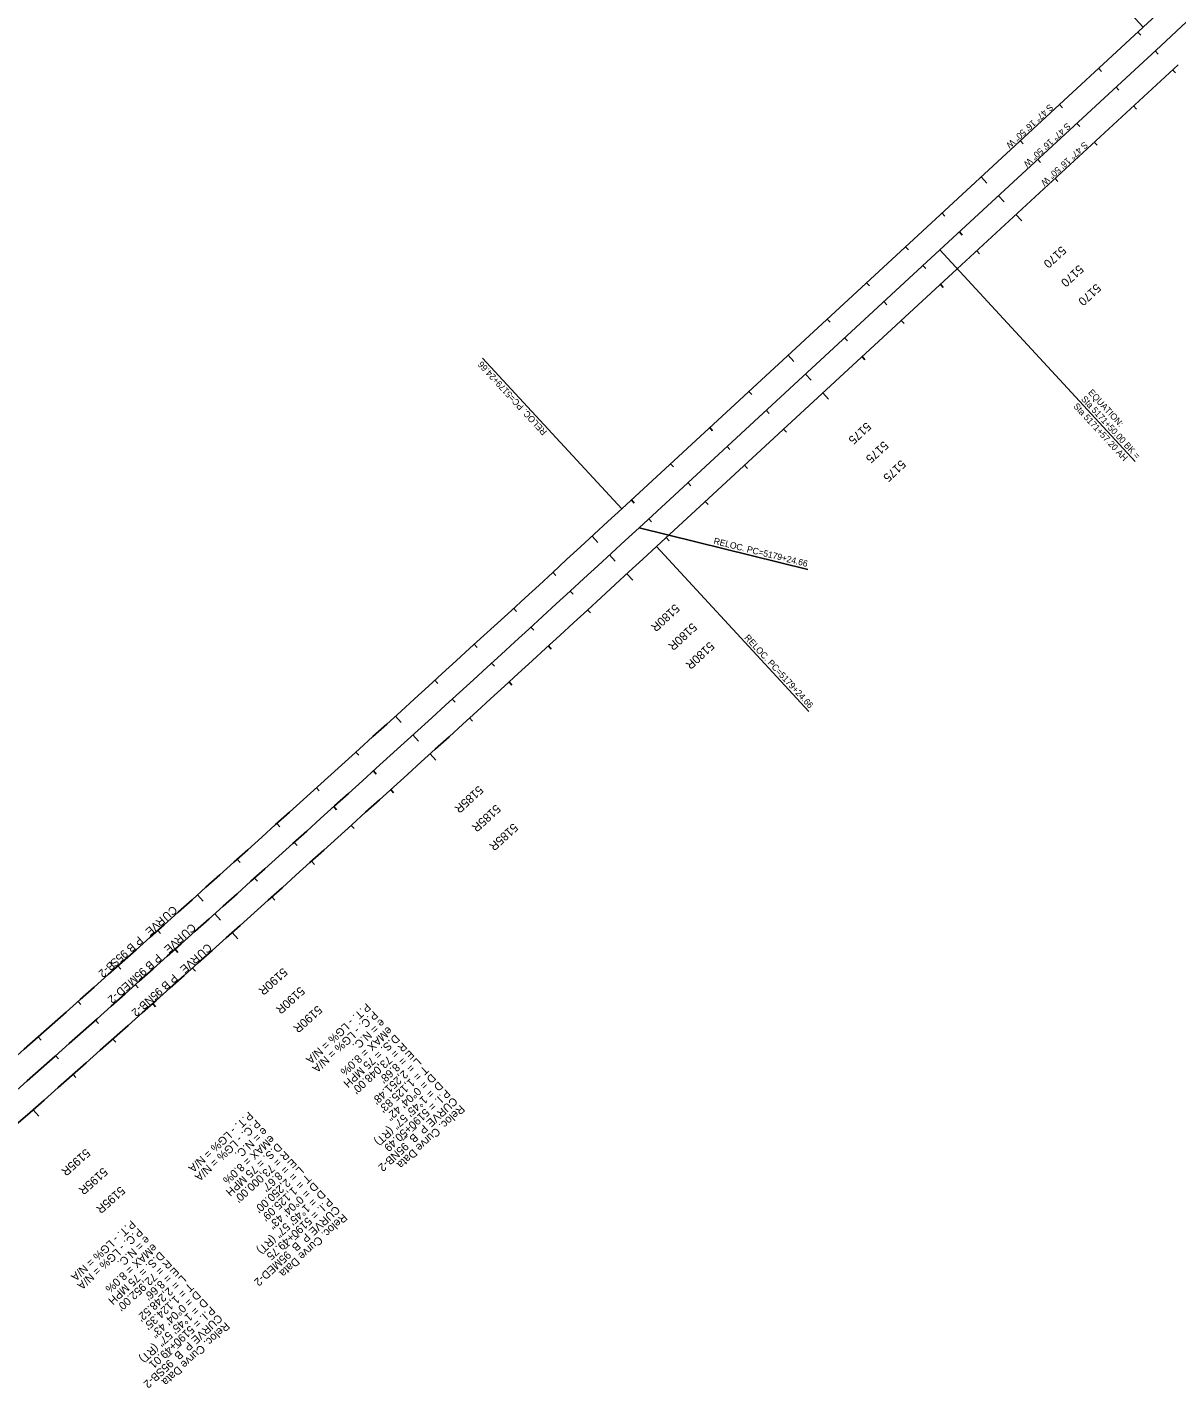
# Model space of a CAD drawing. Extents: x 2161211 to 2175594, y 601812 to 617732.
# Drawn here: x 2170529 to 2172684, y 611607 to 614158 of the extents above; entities that cross this region are included whole.
import ezdxf

# ---------------------------------------------------------------- set-up
doc = ezdxf.new("R2010")
doc.units = 0
for name, color, linetype in [('RD_HC_Cl', 7, 'Continuous'), ('RD_HC_CL_Rel', 7, 'Continuous'), ('RD_HC_Data', 7, 'Continuous'), ('RD_HC_Data_Rel', 7, 'Continuous'), ('RD_HC_Data_Tic', 7, 'Continuous'), ('RD_HC_Data_Tic_Rel', 7, 'Continuous'), ('RD_HC_TX_Rel_Sta50', 7, 'Continuous'), ('RD_HC_TX_Sta50', 7, 'Continuous')]:
    doc.layers.add(name, color=color, linetype=linetype)

msp = doc.modelspace()

# ---------------------------------------------------------------- linework, layer by layer
at = {"layer": 'RD_HC_Cl'}
for p, q in [((2172621.5, 614157.6), (2172207.3, 613775.1)), ((2172654, 614122.3), (2172239.9, 613739.9)), ((2172686.6, 614087), (2172272.5, 613704.6)), ((2172207.3, 613775.1), (2171643.5, 613254.5)), ((2172239.9, 613739.9), (2171676, 613219.2)), ((2172272.5, 613704.6), (2171708.6, 613184))]:
    msp.add_line(p, q, dxfattribs=at)
for radius, end in [(14276, 327.03525), (14324, 326.63611)]:
    msp.add_arc((2162936.5, 624645.9), radius, 312.71947, end, dxfattribs=at)
at = {"layer": 'RD_HC_CL_Rel'}
for radius in [72952, 73000, 73048]:
    msp.add_arc((2122152.2, 666851.2), radius, 310.953509, 312.719474, dxfattribs=at)
at = {"layer": 'RD_HC_Data'}
for p, q in [((2172621.5, 614157.6), (2172553.5, 614231.1)), ((2172239.9, 613739.9), (2172606.2, 613343.1))]:
    msp.add_line(p, q, dxfattribs=at)
at = {"layer": 'RD_HC_Data_Rel'}
for p, q in [((2171643.5, 613254.5), (2171382.6, 613537)), ((2171676, 613219.2), (2171992.3, 613141.1)), ((2171708.6, 613184), (2171994.3, 612874.6))]:
    msp.add_line(p, q, dxfattribs=at)
at = {"layer": 'RD_HC_Data_Tic'}
for p, q in [((2172611.4, 614148.3), (2172616.8, 614142.4)), ((2172644, 614113), (2172649.4, 614107.1)), ((2172537.9, 614080.4), (2172543.4, 614074.5)), ((2172676.5, 614077.7), (2172682, 614071.9)), ((2172570.5, 614045.2), (2172575.9, 614039.3)), ((2172464.5, 614012.6), (2172469.9, 614006.7)), ((2172603.1, 614009.9), (2172608.5, 614004)), ((2172497, 613977.3), (2172502.5, 613971.4)), ((2172391, 613944.7), (2172396.4, 613938.9)), ((2172529.6, 613942.1), (2172535, 613936.2)), ((2172423.6, 613909.5), (2172429, 613903.6)), ((2172317.5, 613876.9), (2172328.4, 613865.1)), ((2172456.1, 613874.2), (2172461.5, 613868.3)), ((2172350.1, 613841.6), (2172360.9, 613829.9)), ((2172244.1, 613809.1), (2172249.5, 613803.2)), ((2172382.7, 613806.4), (2172393.5, 613794.6)), ((2172276.6, 613773.8), (2172282, 613767.9)), ((2172175.9, 613746.1), (2172181.3, 613740.2)), ((2172309.2, 613738.5), (2172314.6, 613732.7)), ((2172208.4, 613710.8), (2172213.9, 613705)), ((2172102.4, 613678.3), (2172107.8, 613672.4)), ((2172241, 613675.6), (2172246.4, 613669.7)), ((2172135, 613643), (2172140.4, 613637.1)), ((2172028.9, 613610.4), (2172034.4, 613604.5)), ((2172167.5, 613607.7), (2172173, 613601.9)), ((2172061.5, 613575.2), (2172066.9, 613569.3)), ((2171955.5, 613542.6), (2171966.3, 613530.8)), ((2172094.1, 613539.9), (2172099.5, 613534)), ((2171988, 613507.3), (2171998.9, 613495.6)), ((2171882, 613474.7), (2171887.4, 613468.9)), ((2172020.6, 613472.1), (2172031.5, 613460.3)), ((2171914.6, 613439.5), (2171920, 613433.6)), ((2171808.5, 613406.9), (2171814, 613401)), ((2171947.1, 613404.2), (2171952.6, 613398.3)), ((2171841.1, 613371.6), (2171846.5, 613365.8)), ((2171735.1, 613339.1), (2171740.5, 613333.2)), ((2171873.7, 613336.4), (2171879.1, 613330.5)), ((2171767.6, 613303.8), (2171773.1, 613297.9)), ((2171661.6, 613271.2), (2171667, 613265.3)), ((2171800.2, 613268.5), (2171805.6, 613262.7)), ((2171694.2, 613236), (2171699.6, 613230.1)), ((2171726.7, 613200.7), (2171732.2, 613194.8))]:
    msp.add_line(p, q, dxfattribs=at)
at = {"layer": 'RD_HC_Data_Tic_Rel'}
for p, q in [((2171588.1, 613203.4), (2171598.9, 613191.6)), ((2171620.7, 613168.1), (2171631.5, 613156.4)), ((2171514.5, 613135.7), (2171519.9, 613129.8)), ((2171653.2, 613132.9), (2171664.1, 613121.1)), ((2171547.1, 613100.4), (2171552.5, 613094.5)), ((2171440.8, 613068.1), (2171446.2, 613062.2)), ((2171579.6, 613065.2), (2171585.1, 613059.3)), ((2171473.4, 613032.8), (2171478.8, 613026.9)), ((2171367.1, 613000.6), (2171372.5, 612994.7)), ((2171506, 612997.5), (2171511.4, 612991.7)), ((2171399.6, 612965.3), (2171405, 612959.4)), ((2171293.2, 612933.2), (2171298.6, 612927.2)), ((2171432.2, 612930), (2171437.6, 612924.1)), ((2171325.8, 612897.9), (2171331.2, 612892)), ((2171219.3, 612865.8), (2171230, 612854)), ((2171358.3, 612862.6), (2171363.7, 612856.7)), ((2171251.8, 612830.6), (2171262.6, 612818.7)), ((2171145.2, 612798.6), (2171150.6, 612792.7)), ((2171284.4, 612795.3), (2171295.1, 612783.5)), ((2171177.8, 612763.4), (2171183.1, 612757.4)), ((2171071.1, 612731.5), (2171076.4, 612725.6)), ((2171210.3, 612728.1), (2171215.7, 612722.2)), ((2171103.6, 612696.3), (2171109, 612690.3)), ((2170996.8, 612664.5), (2171002.2, 612658.6)), ((2171136.2, 612661), (2171141.6, 612655.1)), ((2171029.4, 612629.3), (2171034.8, 612623.3)), ((2170922.5, 612597.6), (2170927.9, 612591.7)), ((2171062, 612594), (2171067.3, 612588)), ((2170955.1, 612562.4), (2170960.4, 612556.4)), ((2170848.1, 612530.8), (2170858.8, 612518.9)), ((2170987.6, 612527.1), (2170993, 612521.1)), ((2170880.7, 612495.5), (2170891.3, 612483.6)), ((2170773.6, 612464.1), (2170778.9, 612458.2)), ((2170913.2, 612460.3), (2170923.9, 612448.4)), ((2170806.2, 612428.8), (2170811.5, 612422.9)), ((2170699, 612397.5), (2170704.3, 612391.5)), ((2170838.7, 612393.6), (2170844.1, 612387.6)), ((2170731.6, 612362.3), (2170736.9, 612356.3)), ((2170624.3, 612331), (2170629.6, 612325)), ((2170764.1, 612327), (2170769.5, 612321)), ((2170656.9, 612295.8), (2170662.2, 612289.8)), ((2170549.5, 612264.6), (2170554.8, 612258.6)), ((2170689.4, 612260.5), (2170694.8, 612254.5)), ((2170582.1, 612229.4), (2170587.4, 612223.4)), ((2170614.7, 612194.1), (2170620, 612188.1)), ((2170539.8, 612127.8), (2170550.4, 612115.8))]:
    msp.add_line(p, q, dxfattribs=at)

# ---------------------------------------------------------------- texts
at = {"layer": 'RD_HC_Data'}
for s, rotation, p in [('S 47%%d 16\' 50" W', 222.7195, (2172445.8, 614014.4)), ('S 47%%d 16\' 50" W', 222.7195, (2172478.4, 613979.2)), ('S 47%%d 16\' 50" W', 222.7195, (2172510.9, 613943.9)), ('EQUATION:', 312.7195, (2172517.2, 613472)), ('Sta 5171+57.20 AH', 312.7195, (2172489.3, 613446.2)), ('Sta 5171+50.00 BK = ', 312.7195, (2172504, 613459.8))]:
    msp.add_text(s, height=12, rotation=rotation, dxfattribs=at).set_placement(p)
at = {"layer": 'RD_HC_Data_Rel'}
for s, height, rotation, p in [('RELOC. PC=5179+24.66', 12, 132.7195, (2171504.3, 613399.4)), ('RELOC. PC=5179+24.66', 12, 346.1298, (2171814.9, 613189)), ('RELOC. PC=5179+24.66', 12, 312.7195, (2171872.6, 613012.3)), ('C', 15, 221.832, (2170801.9, 612511.6)), ('V', 15, 221.7974, (2170769, 612482.2)), ('R', 15, 221.808, (2170779.1, 612491.1)), ('U', 15, 221.8205, (2170790.9, 612501.8)), ('P', 15, 221.7645, (2170737.8, 612454.2)), ('E', 15, 221.7868, (2170759, 612473.2)), ('R', 15, 221.8111, (2170814.1, 612458)), ('U', 15, 221.8236, (2170825.9, 612468.7)), ('C', 15, 221.8351, (2170836.9, 612478.5)), ('9', 15, 221.7346, (2170709.5, 612429)), ('B', 15, 221.7496, (2170723.6, 612441.6)), ('E', 15, 221.79, (2170794, 612440.1)), ('V', 15, 221.8005, (2170804, 612449.1)), ('U', 15, 221.8215, (2170855.9, 612431.1)), ('C', 15, 221.833, (2170866.8, 612440.9)), ('B', 15, 221.7087, (2170684.8, 612407)), ('S', 15, 221.7173, (2170693, 612414.3)), ('5', 15, 221.726, (2170701.3, 612421.6)), ('B', 15, 221.7528, (2170758.6, 612408.5)), ('P', 15, 221.7676, (2170772.8, 612421.1)), ('E', 15, 221.7879, (2170824, 612402.5)), ('V', 15, 221.7984, (2170834, 612411.5)), ('R', 15, 221.809, (2170844, 612420.5)), ('2', 15, 221.6923, (2170669.3, 612393.1)), ('-', 15, 221.6981, (2170674.8, 612398)), ('M', 15, 221.7206, (2170728, 612381.2)), ('5', 15, 221.7292, (2170736.3, 612388.5)), ('9', 15, 221.7379, (2170744.5, 612395.9)), ('P', 15, 221.7655, (2170802.7, 612383.6)), ('D', 15, 221.6956, (2170704.3, 612360)), ('E', 15, 221.7062, (2170714.3, 612369)), ('5', 15, 221.7271, (2170766.2, 612351)), ('9', 15, 221.7358, (2170774.4, 612358.3)), ('B', 15, 221.7507, (2170788.6, 612370.9)), ('2', 15, 221.6773, (2170686.9, 612344.6)), ('-', 15, 221.6831, (2170692.4, 612349.5)), ('B', 15, 221.707, (2170747, 612333.8)), ('N', 15, 221.7185, (2170758, 612343.6)), ('P.T. - LG% = N/A', 15, 222.7195, (2171164.6, 612328.9)), ('2', 15, 221.6906, (2170731.5, 612320)), ('-', 15, 221.6964, (2170737, 612324.9)), ('P.C. - LG% = N/A', 15, 222.7195, (2171178.1, 612314.2)), ('e = N.C.', 15, 222.7195, (2171191.7, 612299.5)), ('eMAX = 8.0%', 15, 222.7195, (2171205.3, 612284.9)), ('D.S. = 75 MPH', 15, 222.7195, (2171218.9, 612270.2)), ("R = 73,048.00'", 15, 222.7195, (2171232.4, 612255.5)), ("L = 2,251.48'", 15, 222.7195, (2171259.6, 612226.1)), ("E = 8.68'", 15, 222.7195, (2171246, 612240.8)), ("T = 1,125.83'", 15, 222.7195, (2171273.1, 612211.4)), ('D = 0°04\' 42"', 15, 222.7195, (2171286.7, 612196.7)), ('D', 15, 222.7195, (2171300.3, 612182)), ('    = 1°45\' 57" (RT)', 15, 222.7195, (2171300.3, 612182)), ('CURVE P_B_95NB-2', 15, 222.7195, (2171327.4, 612152.6)), ('P.I. = 5190+50.49', 15, 222.7195, (2171313.8, 612167.3)), ('P.T. - LG% = N/A', 15, 222.7195, (2170944.2, 612125.4)), ('Reloc. Curve Data', 15, 222.7195, (2171341, 612137.9)), ('P.C. - LG% = N/A', 15, 222.7195, (2170957.7, 612110.7)), ('e = N.C.', 15, 222.7195, (2170971.3, 612096)), ('eMAX = 8.0%', 15, 222.7195, (2170984.9, 612081.3)), ('D.S. = 75 MPH', 15, 222.7195, (2170998.4, 612066.6)), ("R = 73,000.00'", 15, 222.7195, (2171012, 612051.9)), ("L = 2,250.00'", 15, 222.7195, (2171039.2, 612022.6)), ("E = 8.67'", 15, 222.7195, (2171025.6, 612037.3)), ("T = 1,125.09'", 15, 222.7195, (2171052.7, 612007.9)), ('D = 0°04\' 43"', 15, 222.7195, (2171066.3, 611993.2)), ('D', 15, 222.7195, (2171079.9, 611978.5)), ('CURVE P_B_95MED-2', 15, 222.7195, (2171107, 611949.1)), ('    = 1°45\' 57" (RT)', 15, 222.7195, (2171079.9, 611978.5)), ('P.I. = 5190+49.75', 15, 222.7195, (2171093.4, 611963.8)), ('P.T. - LG% = N/A', 15, 222.7195, (2170723.8, 611921.9)), ('Reloc. Curve Data', 15, 222.7195, (2171120.6, 611934.4)), ('P.C. - LG% = N/A', 15, 222.7195, (2170737.3, 611907.2)), ('e = N.C.', 15, 222.7195, (2170750.9, 611892.5)), ('eMAX = 8.0%', 15, 222.7195, (2170764.5, 611877.8)), ('D.S. = 75 MPH', 15, 222.7195, (2170778, 611863.1)), ("R = 72,952.00'", 15, 222.7195, (2170791.6, 611848.4)), ("L = 2,248.52'", 15, 222.7195, (2170818.7, 611819)), ("E = 8.66'", 15, 222.7195, (2170805.2, 611833.7)), ("T = 1,124.35'", 15, 222.7195, (2170832.3, 611804.3)), ('D = 0°04\' 43"', 15, 222.7195, (2170845.9, 611789.6)), ('D', 15, 222.7195, (2170859.5, 611775)), ('    = 1°45\' 57" (RT)', 15, 222.7195, (2170859.5, 611775)), ('CURVE P_B_95SB-2', 15, 222.7195, (2170886.6, 611745.6)), ('P.I. = 5190+49.01', 15, 222.7195, (2170873, 611760.3)), ('Reloc. Curve Data', 15, 222.7195, (2170900.2, 611730.9))]:
    msp.add_text(s, height=height, rotation=rotation, dxfattribs=at).set_placement(p)
at = {"layer": 'RD_HC_TX_Rel_Sta50'}
for s, rotation, p in [('5180R', 222.6603, (2171743.2, 613077.2)), ('5180R', 222.6603, (2171775.7, 613041.9)), ('5180R', 222.6604, (2171808.3, 613006.6)), ('5185R', 222.2676, (2171375.2, 612736.7)), ('5185R', 222.2679, (2171407.7, 612701.4)), ('5185R', 222.2682, (2171440.3, 612666.2)), ('5190R', 221.8749, (2171008.1, 612395.1)), ('5190R', 221.8755, (2171040.6, 612359.8)), ('5190R', 221.876, (2171073.2, 612324.5)), ('5195R', 221.4822, (2170638.5, 612056)), ('5195R', 221.483, (2170671.1, 612020.7)), ('5195R', 221.4838, (2170703.7, 611985.5))]:
    msp.add_text(s, height=16, rotation=rotation, dxfattribs=at).set_placement(p)
at = {"layer": 'RD_HC_TX_Sta50'}
for s, p in [('5170', (2172468, 613748.4)), ('5170', (2172500.6, 613713.1)), ('5170', (2172533.1, 613677.8)), ('5175', (2172102.2, 613418)), ('5175', (2172134.7, 613382.7)), ('5175', (2172167.3, 613347.5))]:
    msp.add_text(s, height=16, rotation=222.7195, dxfattribs=at).set_placement(p)

doc.saveas('drawing.dxf')
